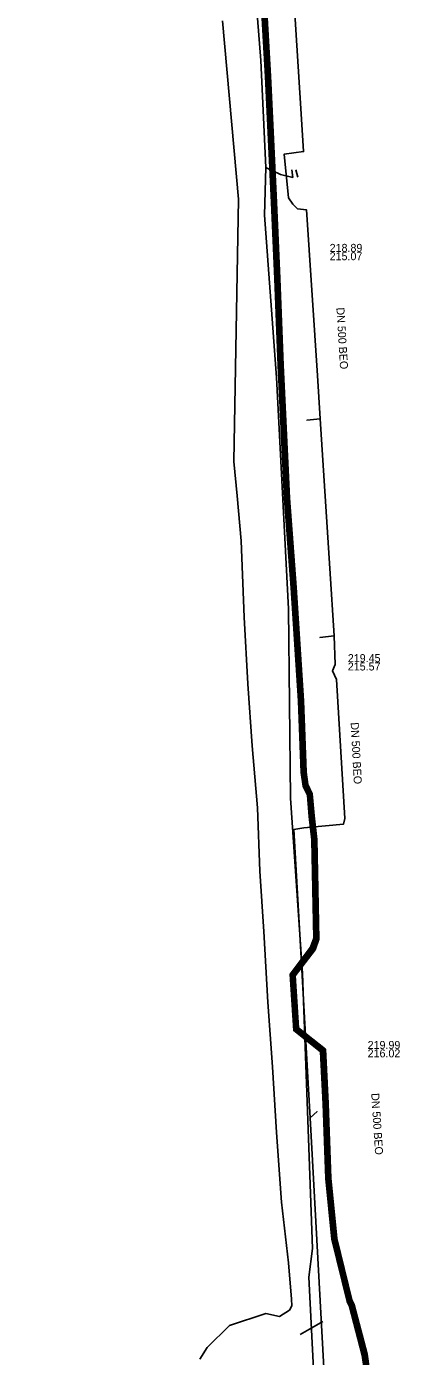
# Model space of a CAD drawing. Extents: x -599951 to -598963, y -1164095 to -1162939.
# Drawn here: x -599238.3 to -599200.6, y -1163707.4 to -1163574.5 of the extents above; entities that cross this region are included whole.
import ezdxf

# ---------------------------------------------------------------- set-up
doc = ezdxf.new("R2010")
doc.units = 0
for name, color, linetype in [('Vrstva 12', 7, 'Continuous'), ('Vrstva 42', 7, 'Continuous'), ('Vrstva 44', 7, 'Continuous'), ('Vrstva 55', 7, 'Continuous'), ('Vrstva 58', 7, 'Continuous')]:
    doc.layers.add(name, color=color, linetype=linetype)

msp = doc.modelspace()

# ---------------------------------------------------------------- linework, layer by layer
at = {"layer": 'Vrstva 42'}
for points in [[(-599211.757, -1163588.838), (-599211.66, -1163589.578), (-599212.89, -1163589.29), (-599214.35, -1163588.59), (-599214.84, -1163577.9), (-599216.2, -1163560.96), (-599216.62, -1163543.04), (-599219.31, -1163511.2), (-599221.85, -1163490.32), (-599224.61, -1163458.23), (-599225.84, -1163434.22), (-599226.77, -1163411.87), (-599227.39, -1163399.73), (-599228, -1163379.96), (-599229.84, -1163349.61), (-599231.04, -1163328.77), (-599232.25, -1163300.34), (-599232.78, -1163281.98), (-599233.12, -1163279.09), (-599233.85, -1163272.58), (-599234.55, -1163261.34), (-599236.04, -1163234.14), (-599238.28, -1163193.96)], [(-599211.757, -1163588.838), (-599211.66, -1163589.578), (-599212.89, -1163589.29), (-599214.35, -1163588.59), (-599214.84, -1163577.9), (-599216.2, -1163560.96), (-599216.62, -1163543.04), (-599219.31, -1163511.2), (-599221.85, -1163490.32), (-599224.61, -1163458.23), (-599225.84, -1163434.22), (-599226.77, -1163411.87), (-599227.39, -1163399.73), (-599228, -1163379.96), (-599229.84, -1163349.61), (-599231.04, -1163328.77), (-599232.25, -1163300.34), (-599232.78, -1163281.98), (-599233.12, -1163279.09), (-599233.85, -1163272.58), (-599234.55, -1163261.34), (-599236.04, -1163234.14), (-599238.28, -1163193.96)], [(-599214.49, -1163593.34), (-599214.35, -1163588.59), (-599214.84, -1163577.9), (-599216.2, -1163560.96), (-599216.62, -1163543.04), (-599219.31, -1163511.2), (-599221.85, -1163490.32), (-599224.61, -1163458.23), (-599225.84, -1163434.22), (-599226.77, -1163411.87), (-599227.39, -1163399.73), (-599228, -1163379.96), (-599229.84, -1163349.61), (-599231.04, -1163328.77), (-599232.25, -1163300.34), (-599232.78, -1163281.98), (-599233.12, -1163279.09), (-599233.85, -1163272.58), (-599234.55, -1163261.34), (-599236.04, -1163234.14), (-599238.28, -1163193.96)], [(-599214.49, -1163593.34), (-599214.35, -1163588.59), (-599214.84, -1163577.9), (-599216.2, -1163560.96), (-599216.62, -1163543.04), (-599219.31, -1163511.2), (-599221.85, -1163490.32), (-599224.61, -1163458.23), (-599225.84, -1163434.22), (-599226.77, -1163411.87), (-599227.39, -1163399.73), (-599228, -1163379.96), (-599229.84, -1163349.61), (-599231.04, -1163328.77), (-599232.25, -1163300.34), (-599232.78, -1163281.98), (-599233.12, -1163279.09), (-599233.85, -1163272.58), (-599234.55, -1163261.34), (-599236.04, -1163234.14), (-599238.28, -1163193.96)], [(-599209.19, -1163716.57), (-599210.04, -1163699.48), (-599209.68, -1163696.63), (-599210.7, -1163669.15), (-599211.89, -1163651.61), (-599212.1, -1163632.7), (-599213.28, -1163609.58), (-599214.49, -1163593.34), (-599214.35, -1163588.59), (-599214.84, -1163577.9), (-599216.2, -1163560.96), (-599216.62, -1163543.04), (-599219.31, -1163511.2), (-599221.85, -1163490.32), (-599224.61, -1163458.23), (-599225.84, -1163434.22)], [(-599225.84, -1163434.22), (-599224.61, -1163458.23), (-599221.85, -1163490.32), (-599219.31, -1163511.2), (-599216.62, -1163543.04), (-599216.2, -1163560.96), (-599214.84, -1163577.9), (-599214.35, -1163588.59), (-599214.49, -1163593.34), (-599213.28, -1163609.58), (-599212.1, -1163632.7), (-599211.89, -1163651.61), (-599210.7, -1163669.15), (-599209.68, -1163696.63), (-599210.04, -1163699.48), (-599209.19, -1163716.57)], [(-599209.19, -1163716.57), (-599210.04, -1163699.48), (-599209.68, -1163696.63), (-599210.7, -1163669.15), (-599211.89, -1163651.61), (-599212.1, -1163632.7), (-599213.28, -1163609.58), (-599214.49, -1163593.34), (-599214.35, -1163588.59), (-599214.84, -1163577.9), (-599216.2, -1163560.96), (-599216.62, -1163543.04), (-599219.31, -1163511.2), (-599221.85, -1163490.32), (-599224.61, -1163458.23), (-599225.84, -1163434.22)], [(-599211.757, -1163588.838), (-599211.66, -1163589.578), (-599212.89, -1163589.29), (-599214.35, -1163588.59), (-599214.49, -1163593.34), (-599213.28, -1163609.58), (-599212.1, -1163632.7), (-599211.89, -1163651.61), (-599210.7, -1163669.15), (-599209.68, -1163696.63), (-599210.04, -1163699.48), (-599209.19, -1163716.57), (-599208.58, -1163738.66), (-599206.82, -1163772.03), (-599205.21, -1163812.07), (-599203.78, -1163853.21), (-599203.16, -1163874.53), (-599200.61, -1163874.5), (-599200.591, -1163873.943)], [(-599211.757, -1163588.838), (-599211.66, -1163589.578), (-599212.89, -1163589.29), (-599214.35, -1163588.59), (-599214.49, -1163593.34), (-599213.28, -1163609.58), (-599212.1, -1163632.7), (-599211.89, -1163651.61), (-599210.7, -1163669.15), (-599209.68, -1163696.63), (-599210.04, -1163699.48), (-599209.19, -1163716.57), (-599208.58, -1163738.66), (-599206.82, -1163772.03), (-599205.21, -1163812.07), (-599203.78, -1163853.21), (-599203.16, -1163874.53), (-599200.61, -1163874.5), (-599200.591, -1163873.943)], [(-599214.35, -1163588.59), (-599212.89, -1163589.29), (-599211.66, -1163589.578), (-599211.757, -1163588.838)], [(-599211.361, -1163588.838), (-599211.163, -1163589.575)], [(-599211.361, -1163588.838), (-599211.163, -1163589.575)], [(-599211.361, -1163588.838), (-599211.163, -1163589.575)], [(-599209.19, -1163716.57), (-599210.04, -1163699.48), (-599209.68, -1163696.63), (-599210.7, -1163669.15), (-599211.89, -1163651.61), (-599212.1, -1163632.7), (-599213.28, -1163609.58), (-599214.49, -1163593.34)], [(-599209.19, -1163716.57), (-599210.04, -1163699.48), (-599209.68, -1163696.63), (-599210.7, -1163669.15), (-599211.89, -1163651.61), (-599212.1, -1163632.7), (-599213.28, -1163609.58), (-599214.49, -1163593.34)], [(-599209.971, -1163704.68), (-599210.933, -1163705.226)], [(-599208.667, -1163703.939), (-599209.971, -1163704.68)]]:
    msp.add_lwpolyline(points, dxfattribs=at)
at = {"layer": 'Vrstva 44'}
for points in [[(-599214.74, -1163571.282), (-599214.3, -1163579.49), (-599213.7, -1163592.089), (-599213.34, -1163599.709), (-599213.01, -1163608.368), (-599212.39, -1163621.652), (-599211.71, -1163630.584), (-599210.99, -1163641.9), (-599210.729, -1163649.048), (-599210.533, -1163650.389), (-599210.096, -1163651.304), (-599209.909, -1163653.43), (-599209.65, -1163655.783), (-599209.461, -1163665.638), (-599209.788, -1163666.574), (-599211.824, -1163669.248), (-599211.464, -1163674.791), (-599208.785, -1163676.92), (-599208.51, -1163682.159), (-599208.25, -1163689.613), (-599207.658, -1163695.694), (-599206.139, -1163701.899), (-599205.888, -1163702.401), (-599204.607, -1163707.268), (-599204.4, -1163708.881)], [(-599204.2, -1163708.87), (-599204.41, -1163707.23), (-599205.699, -1163702.332), (-599205.95, -1163701.83), (-599207.46, -1163695.66), (-599208.05, -1163689.6), (-599208.31, -1163682.15), (-599208.59, -1163676.82), (-599211.27, -1163674.69), (-599211.62, -1163669.31), (-599209.61, -1163666.67), (-599209.26, -1163665.67), (-599209.451, -1163655.763), (-599209.71, -1163653.41), (-599209.9, -1163651.25), (-599210.34, -1163650.33), (-599210.53, -1163649.038), (-599210.79, -1163641.89), (-599211.51, -1163630.574), (-599212.19, -1163621.642), (-599212.81, -1163608.358), (-599213.14, -1163599.71), (-599213.5, -1163592.09), (-599214.1, -1163579.491), (-599214.54, -1163571.283)], [(-599204, -1163708.859), (-599204.213, -1163707.192), (-599205.511, -1163702.261), (-599205.761, -1163701.761), (-599207.262, -1163695.626), (-599207.85, -1163689.587), (-599208.11, -1163682.141), (-599208.395, -1163676.72), (-599211.076, -1163674.589), (-599211.416, -1163669.372), (-599209.432, -1163666.766), (-599209.059, -1163665.702), (-599209.251, -1163655.75), (-599209.511, -1163653.39), (-599209.704, -1163651.196), (-599210.146, -1163650.271), (-599210.33, -1163649.02), (-599210.59, -1163641.88), (-599211.31, -1163630.56), (-599211.99, -1163621.63), (-599212.61, -1163608.35), (-599212.94, -1163599.701), (-599213.3, -1163592.081), (-599213.9, -1163579.481), (-599214.34, -1163571.271)], [(-599220.95, -1163707.7), (-599220.22, -1163706.51), (-599217.98, -1163704.33), (-599214.36, -1163703.14), (-599212.97, -1163703.42), (-599211.99, -1163702.8), (-599211.74, -1163702.35), (-599211.77, -1163701.69), (-599212.07, -1163698.06), (-599212.78, -1163692), (-599213.27, -1163685.04), (-599213.69, -1163678.48), (-599214.15, -1163672.02), (-599214.56, -1163664.96), (-599214.94, -1163658.93), (-599215.18, -1163652.6), (-599215.71, -1163646.4), (-599216.14, -1163640.18), (-599216.52, -1163633.53), (-599216.83, -1163625.89), (-599217.23, -1163621.41), (-599217.55, -1163617.98), (-599217.09, -1163591.75), (-599218.7, -1163573.95)]]:
    msp.add_lwpolyline(points, dxfattribs=at)
at = {"layer": 'Vrstva 55'}
for points in [[(-599211.586, -1163571.108), (-599210.785, -1163583.756), (-599210.58, -1163587), (-599212.52, -1163587.27), (-599212.09, -1163591.62), (-599211.64, -1163592.27), (-599211.18, -1163592.71), (-599210.3, -1163592.81), (-599209.198, -1163609.365), (-599208.91, -1163613.7), (-599210.25, -1163613.85), (-599208.91, -1163613.7), (-599207.951, -1163628.683), (-599207.52, -1163635.41), (-599208.94, -1163635.56), (-599207.52, -1163635.41), (-599207.42, -1163638.27), (-599207.67, -1163638.89), (-599207.29, -1163639.75), (-599206.45, -1163653.65), (-599206.58, -1163654.21), (-599210.56, -1163654.59), (-599211.55, -1163654.74), (-599210.82, -1163667.573), (-599210.073, -1163680.711), (-599209.91, -1163683.58), (-599209.227, -1163682.94), (-599209.91, -1163683.58)], [(-599209.91, -1163683.58), (-599208.92, -1163701.85), (-599208.39, -1163711.57)]]:
    msp.add_lwpolyline(points, dxfattribs=at)
at = {"layer": 'Vrstva 58'}
for points in [[(-599214.839, -1163571.288), (-599214.4, -1163579.495), (-599213.8, -1163592.094), (-599213.44, -1163599.713), (-599213.11, -1163608.373), (-599212.489, -1163621.658), (-599211.809, -1163630.591), (-599211.09, -1163641.905), (-599210.829, -1163649.057), (-599210.63, -1163650.418), (-599210.194, -1163651.33), (-599210.009, -1163653.44), (-599209.75, -1163655.789), (-599209.561, -1163665.622), (-599209.877, -1163666.526), (-599211.927, -1163669.217), (-599211.561, -1163674.842), (-599208.882, -1163676.971), (-599208.61, -1163682.163), (-599208.35, -1163689.62), (-599207.756, -1163695.71), (-599206.233, -1163701.934)], [(-599206.044, -1163701.865), (-599207.559, -1163695.677), (-599208.15, -1163689.607), (-599208.41, -1163682.154), (-599208.687, -1163676.87), (-599211.367, -1163674.741), (-599211.722, -1163669.279), (-599209.699, -1163666.622), (-599209.36, -1163665.654), (-599209.55, -1163655.776), (-599209.81, -1163653.42), (-599209.998, -1163651.277), (-599210.437, -1163650.359), (-599210.63, -1163649.039), (-599210.89, -1163641.895), (-599211.61, -1163630.577), (-599212.29, -1163621.646), (-599212.91, -1163608.364), (-599213.24, -1163599.704), (-599213.6, -1163592.085), (-599214.2, -1163579.485), (-599214.64, -1163571.276)], [(-599205.856, -1163701.795), (-599207.361, -1163695.643), (-599207.95, -1163689.593), (-599208.21, -1163682.146), (-599208.492, -1163676.77), (-599211.173, -1163674.639), (-599211.518, -1163669.341), (-599209.521, -1163666.718), (-599209.16, -1163665.686), (-599209.35, -1163655.764), (-599209.61, -1163653.4), (-599209.802, -1163651.223), (-599210.243, -1163650.301), (-599210.43, -1163649.021), (-599210.69, -1163641.885), (-599211.41, -1163630.563), (-599212.09, -1163621.634), (-599212.71, -1163608.356), (-599213.04, -1163599.696), (-599213.4, -1163592.075), (-599214, -1163579.475), (-599214.44, -1163571.264)], [(-599206.233, -1163701.934), (-599205.982, -1163702.436), (-599204.705, -1163707.287), (-599204.5, -1163708.886)], [(-599204.3, -1163708.875), (-599204.508, -1163707.249), (-599205.794, -1163702.365), (-599206.044, -1163701.865)], [(-599204.1, -1163708.865), (-599204.312, -1163707.211), (-599205.606, -1163702.295), (-599205.856, -1163701.795)]]:
    msp.add_lwpolyline(points, dxfattribs=at)

# ---------------------------------------------------------------- texts
at = {"layer": 'Vrstva 12'}
for s, p in [('218.89', (-599207.97, -1163597.027)), ('215.07', (-599207.97, -1163597.859)), ('219.45', (-599206.153, -1163638.027)), ('215.57', (-599206.153, -1163638.859)), ('219.99', (-599204.171, -1163676.691)), ('216.02', (-599204.171, -1163677.523))]:
    msp.add_text(s, height=0.8, dxfattribs=at).set_placement(p)
for rotation, p in [(273.5333, (-599207.299, -1163602.606)), (272.97951, (-599205.866, -1163644.062)), (273.70463, (-599203.814, -1163681.122))]:
    msp.add_text('DN 500 BEO', height=0.8, rotation=rotation, dxfattribs=at).set_placement(p)

doc.saveas('drawing.dxf')
